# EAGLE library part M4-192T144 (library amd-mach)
AMD MACH SERIES
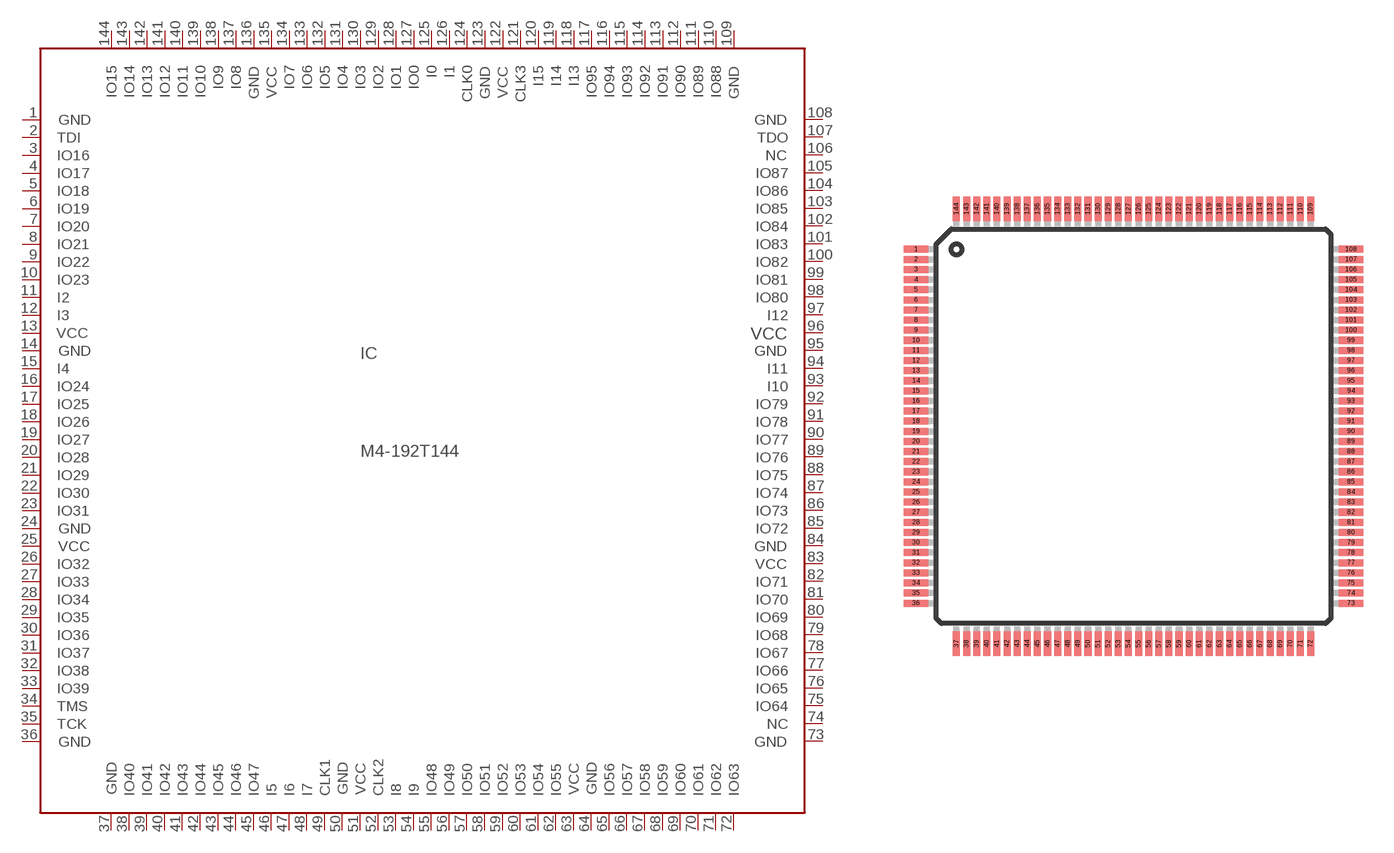
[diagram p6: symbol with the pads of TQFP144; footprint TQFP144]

Designator prefix IC

## M4-192T144 (OC_FARNELL: unknown; OC_NEWARK: unknown)  [TQFP144]
1  GND  pwr
2  TDI  in
3  IO16
4  IO17
5  IO18
6  IO19
7  IO20
8  IO21
9  IO22
10  IO23
11  I2  in
12  I3  in
13  VCC  pwr
14  GND  pwr
15  I4  in
16  IO24
17  IO25
18  IO26
19  IO27
20  IO28
21  IO29
22  IO30
23  IO31
24  GND  pwr
25  VCC  pwr
26  IO32
27  IO33
28  IO34
29  IO35
30  IO36
31  IO37
32  IO38
33  IO39
34  TMS  in
35  TCK  in
36  GND  pwr
37  GND  pwr
38  IO40
39  IO41
40  IO42
41  IO43
42  IO44
43  IO45
44  IO46
45  IO47
46  I5  in
47  I6  in
48  I7  in
49  CLK1  in
50  GND  pwr
51  VCC  pwr
52  CLK2  in
53  I8  in
54  I9  in
55  IO48
56  IO49
57  IO50
58  IO51
59  IO52
60  IO53
61  IO54
62  IO55
63  VCC  pwr
64  GND  pwr
65  IO56
66  IO57
67  IO58
68  IO59
69  IO60
70  IO61
71  IO62
72  IO63
73  GND  pwr
74  NC  nc
75  IO64
76  IO65
77  IO66
78  IO67
79  IO68
80  IO69
81  IO70
82  IO71
83  VCC  pwr
84  GND  pwr
85  IO72
86  IO73
87  IO74
88  IO75
89  IO76
90  IO77
91  IO78
92  IO79
93  I10  in
94  I11  in
95  GND  pwr
96  VCC  pwr
97  I12  in
98  IO80
99  IO81
100  IO82
101  IO83
102  IO84
103  IO85
104  IO86
105  IO87
106  NC1  nc
107  TDO  out
108  GND  pwr
109  GND  pwr
110  IO88
111  IO89
112  IO90
113  IO91
114  IO92
115  IO93
116  IO94
117  IO95
118  I13  in
119  I14  in
120  I15  in
121  CLK3  in
122  VCC  pwr
123  GND  pwr
124  CLK0  in
125  I0  in
126  I1  in
127  IO0
128  IO1
129  IO2
130  IO3
131  IO4
132  IO5
133  IO6
134  IO7
135  VCC  pwr
136  GND  pwr
137  IO8
138  IO9
139  IO10
140  IO11
141  IO12
142  IO13
143  IO14
144  IO15

## Footprint TQFP144 (pad centres in mm)
THIN QUAD FLAT PACK
smd 1.2 x 0.35: 1 -10.75,8.75; 2 -10.75,8.25; 3 -10.75,7.75; 4 -10.75,7.25; 5 -10.75,6.75; 6 -10.75,6.25; 7 -10.75,5.75; 8 -10.75,5.25; 9 -10.75,4.75; 10 -10.75,4.25; 11 -10.75,3.75; 12 -10.75,3.25; 13 -10.75,2.75; 14 -10.75,2.25; 15 -10.75,1.75; 16 -10.75,1.25; 17 -10.75,0.75; 18 -10.75,0.25; 19 -10.75,-0.25; 20 -10.75,-0.75; 21 -10.75,-1.25; 22 -10.75,-1.75; 23 -10.75,-2.25; 24 -10.75,-2.75; 25 -10.75,-3.25; 26 -10.75,-3.75; 27 -10.75,-4.25; 28 -10.75,-4.75; 29 -10.75,-5.25; 30 -10.75,-5.75; 31 -10.75,-6.25; 32 -10.75,-6.75; 33 -10.75,-7.25; 34 -10.75,-7.75; 35 -10.75,-8.25; 36 -10.75,-8.75; 73 10.75,-8.75; 74 10.75,-8.25; 75 10.75,-7.75; 76 10.75,-7.25; 77 10.75,-6.75; 78 10.75,-6.25; 79 10.75,-5.75; 80 10.75,-5.25; 81 10.75,-4.75; 82 10.75,-4.25; 83 10.75,-3.75; 84 10.75,-3.25; 85 10.75,-2.75; 86 10.75,-2.25; 87 10.75,-1.75; 88 10.75,-1.25; 89 10.75,-0.75; 90 10.75,-0.25; 91 10.75,0.25; 92 10.75,0.75; 93 10.75,1.25; 94 10.75,1.75; 95 10.75,2.25; 96 10.75,2.75; 97 10.75,3.25; 98 10.75,3.75; 99 10.75,4.25; 100 10.75,4.75; 101 10.75,5.25; 102 10.75,5.75; 103 10.75,6.25; 104 10.75,6.75; 105 10.75,7.25; 106 10.75,7.75; 107 10.75,8.25; 108 10.75,8.75
smd 0.35 x 1.2: 37 -8.75,-10.75; 38 -8.25,-10.75; 39 -7.75,-10.75; 40 -7.25,-10.75; 41 -6.75,-10.75; 42 -6.25,-10.75; 43 -5.75,-10.75; 44 -5.25,-10.75; 45 -4.75,-10.75; 46 -4.25,-10.75; 47 -3.75,-10.75; 48 -3.25,-10.75; 49 -2.75,-10.75; 50 -2.25,-10.75; 51 -1.75,-10.75; 52 -1.25,-10.75; 53 -0.75,-10.75; 54 -0.25,-10.75; 55 0.25,-10.75; 56 0.75,-10.75; 57 1.25,-10.75; 58 1.75,-10.75; 59 2.25,-10.75; 60 2.75,-10.75; 61 3.25,-10.75; 62 3.75,-10.75; 63 4.25,-10.75; 64 4.75,-10.75; 65 5.25,-10.75; 66 5.75,-10.75; 67 6.25,-10.75; 68 6.75,-10.75; 69 7.25,-10.75; 70 7.75,-10.75; 71 8.25,-10.75; 72 8.75,-10.75; 109 8.75,10.75; 110 8.25,10.75; 111 7.75,10.75; 112 7.25,10.75; 113 6.75,10.75; 114 6.25,10.75; 115 5.75,10.75; 116 5.25,10.75; 117 4.75,10.75; 118 4.25,10.75; 119 3.75,10.75; 120 3.25,10.75; 121 2.75,10.75; 122 2.25,10.75; 123 1.75,10.75; 124 1.25,10.75; 125 0.75,10.75; 126 0.25,10.75; 127 -0.25,10.75; 128 -0.75,10.75; 129 -1.25,10.75; 130 -1.75,10.75; 131 -2.25,10.75; 132 -2.75,10.75; 133 -3.25,10.75; 134 -3.75,10.75; 135 -4.25,10.75; 136 -4.75,10.75; 137 -5.25,10.75; 138 -5.75,10.75; 139 -6.25,10.75; 140 -6.75,10.75; 141 -7.25,10.75; 142 -7.75,10.75; 143 -8.25,10.75; 144 -8.75,10.75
